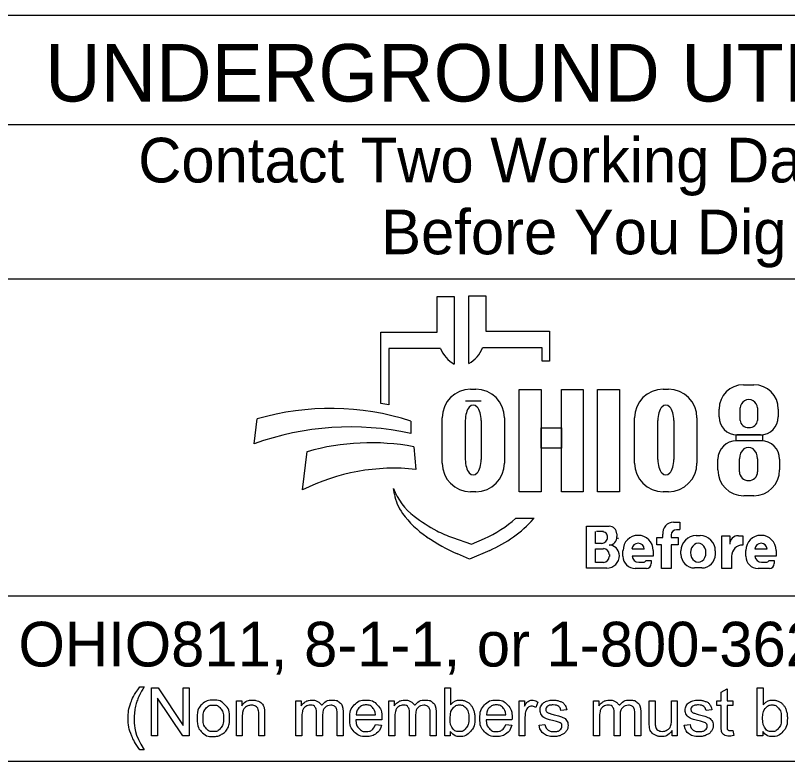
# Model space of a CAD drawing. Extents: x 0 to 170000, y 0 to 110000.
# Drawn here: x 11104 to 23197, y 15901 to 27588 of the extents above; entities that cross this region are included whole.
import ezdxf

# ---------------------------------------------------------------- set-up
doc = ezdxf.new("R2010")
doc.units = 0
doc.layers.add('SH_Data', color=7, linetype='Continuous')
doc.layers.add('SH_Text', color=7, linetype='Continuous')

msp = doc.modelspace()

# ---------------------------------------------------------------- linework, layer by layer
at = {"layer": 'SH_Data'}
for p, q in [((32179, 27588), (10929, 27588)), ((10929, 25880), (32179, 25880)), ((10929, 23463), (32179, 23463)), ((32179, 18490), (10929, 18490)), ((32179, 15901), (10929, 15901))]:
    msp.add_line(p, q, dxfattribs=at)
at = {"layer": 'SH_Text'}
for p, q in [((17709, 22628), (17709, 23186)), ((17709, 23186), (17977, 23186)), ((17977, 23186), (17977, 22125)), ((18205, 22137), (18205, 23197)), ((18205, 23197), (18474, 23197)), ((18474, 23197), (18474, 22640)), ((16829, 21509), (16829, 22628)), ((16829, 22628), (17709, 22628)), ((18474, 22640), (19470, 22640)), ((19470, 22640), (19470, 22171)), ((19353, 22383), (18422, 22383)), ((19353, 22171), (19353, 22383)), ((16955, 22371), (16955, 21487)), ((17761, 22371), (16955, 22371)), ((19470, 22171), (19353, 22171)), ((22507, 21802), (22670, 21802)), ((18234, 21732), (18316, 21732)), ((21249, 21732), (21332, 21732)), ((18400, 21547), (18151, 21547)), ((22125, 21299), (22125, 21421)), ((22456, 21242), (22456, 21439)), ((22727, 21439), (22727, 21242)), ((23052, 21421), (23052, 21299)), ((17786, 20575), (17786, 21285)), ((18764, 21285), (18764, 20575)), ((20802, 20575), (20802, 21285)), ((21779, 21285), (21779, 20575)), ((14842, 20877), (14889, 21268)), ((17296, 21235), (17296, 21041)), ((18151, 20632), (18151, 21243)), ((18400, 21243), (18400, 20632)), ((21166, 20632), (21166, 21243)), ((21415, 21243), (21415, 20632)), ((22396, 20928), (22783, 20928)), ((22772, 21019), (22405, 21019)), ((17345, 20832), (17376, 20478)), ((15601, 20155), (15675, 20755)), ((22107, 20468), (22107, 20638)), ((22444, 20438), (22444, 20643)), ((22728, 20643), (22728, 20438)), ((23072, 20638), (23072, 20468)), ((17040, 20090), (17025, 20180)), ((18316, 20127), (18234, 20127)), ((21332, 20127), (21249, 20127)), ((22667, 20063), (22511, 20063)), ((18941, 19711), (19228, 19711)), ((21411, 19649), (21508, 19649)), ((21508, 19649), (21508, 19535)), ((20048, 18932), (20048, 19586)), ((20048, 19586), (20404, 19586)), ((20188, 19318), (20188, 19503)), ((20314, 19503), (20207, 19503)), ((21508, 19532), (21457, 19532)), ((17949, 19409), (18246, 19306)), ((18246, 19306), (18451, 19395)), ((20522, 19467), (20522, 19427)), ((21148, 19293), (21148, 19408)), ((21148, 19408), (21244, 19408)), ((21244, 19408), (21244, 19460)), ((21375, 19450), (21375, 19408)), ((21375, 19408), (21483, 19408)), ((21483, 19408), (21483, 19293)), ((21767, 19440), (21827, 19440)), ((22168, 18926), (22168, 19439)), ((22168, 19439), (22291, 19439)), ((22291, 19439), (22291, 19305)), ((22427, 19439), (22496, 19439)), ((22496, 19439), (22496, 19291)), ((20285, 19318), (20188, 19318)), ((20188, 19021), (20188, 19235)), ((20188, 19235), (20315, 19235)), ((21222, 19293), (21148, 19293)), ((21222, 18926), (21222, 19293)), ((21483, 19293), (21375, 19293)), ((21375, 19293), (21375, 18926)), ((18216, 19071), (18029, 19153)), ((18532, 19209), (18216, 19071)), ((20406, 19145), (20406, 19113)), ((20563, 19130), (20563, 19129)), ((20620, 19116), (20620, 19208)), ((20953, 19228), (20761, 19228)), ((21093, 19119), (20761, 19119)), ((21093, 19208), (21093, 19119)), ((21528, 19147), (21528, 19201)), ((22066, 19201), (22066, 19147)), ((22321, 19117), (22321, 18926)), ((22545, 19116), (22545, 19208)), ((22878, 19228), (22685, 19228)), ((23018, 19119), (22686, 19119)), ((23018, 19208), (23018, 19119)), ((20314, 19021), (20188, 19021)), ((20866, 19023), (20936, 19023)), ((20979, 19051), (21063, 19051)), ((21063, 19051), (21063, 19002)), ((22790, 19023), (22861, 19023)), ((22904, 19051), (22988, 19051)), ((22988, 19051), (22988, 19002)), ((20366, 18932), (20048, 18932)), ((20987, 18926), (20810, 18926)), ((21375, 18926), (21222, 18926)), ((21853, 18934), (21742, 18934)), ((22321, 18926), (22168, 18926)), ((22912, 18926), (22735, 18926))]:
    msp.add_line(p, q, dxfattribs=at)
for points in [[(18996, 21727), (19336, 21727), (19336, 20127), (18996, 20127)], [(19657, 21727), (19996, 21727), (19996, 20127), (19657, 20127)], [(20223, 21727), (20567, 21727), (20567, 20127), (20223, 20127)], [(19336, 21128), (19657, 21128), (19657, 20808), (19336, 20808)], [(22394, 21019), (22803, 21019), (22803, 20927), (22394, 20927)]]:
    msp.add_lwpolyline(points, close=True, dxfattribs=at)
for points in [[(13052, 17070), (13118, 17070)], [(13235, 16306), (13235, 17057), (13337, 17057), (13732, 16467), (13732, 17057), (13827, 17057), (13827, 16306), (13725, 16306), (13330, 16896), (13330, 16306), (13235, 16306)], [(17913, 16306), (17828, 16306), (17828, 17057), (17920, 17057), (17920, 16789)], [(22808, 16306), (22723, 16306), (22723, 17057), (22815, 17057), (22815, 16789)], [(22157, 16466), (22157, 16779), (22089, 16779), (22089, 16850), (22157, 16850), (22157, 16985), (22250, 17040), (22250, 16850), (22342, 16850), (22342, 16779), (22250, 16779), (22250, 16460)], [(14565, 16306), (14565, 16850), (14648, 16850), (14648, 16773)], [(15497, 16306), (15497, 16850), (15580, 16850), (15580, 16774)], [(16954, 16306), (16954, 16850), (17037, 16850), (17037, 16774)], [(18993, 16306), (18993, 16850), (19076, 16850), (19076, 16768)], [(19288, 16833), (19256, 16748)], [(20159, 16306), (20159, 16850), (20242, 16850), (20242, 16774)], [(21031, 16513), (21031, 16850), (21123, 16850), (21123, 16549)], [(21379, 16559), (21379, 16850), (21471, 16850), (21471, 16306), (21389, 16306)], [(19738, 16710), (19648, 16698)], [(22011, 16710), (21921, 16698)], [(14657, 16603), (14657, 16306), (14565, 16306)], [(15007, 16641), (15007, 16306), (14915, 16306), (14915, 16637)], [(15589, 16588), (15589, 16306), (15497, 16306)], [(15913, 16622), (15913, 16306), (15821, 16306), (15821, 16660)], [(16235, 16680), (16235, 16306), (16143, 16306), (16143, 16649)], [(16440, 16630), (16744, 16630)], [(17046, 16588), (17046, 16306), (16954, 16306)], [(17370, 16622), (17370, 16306), (17278, 16306), (17278, 16660)], [(17692, 16680), (17692, 16306), (17600, 16306), (17600, 16649)], [(18480, 16630), (18784, 16630)], [(19085, 16591), (19085, 16306), (18993, 16306)], [(20251, 16588), (20251, 16306), (20159, 16306)], [(20575, 16622), (20575, 16306), (20483, 16306), (20483, 16660)], [(20897, 16680), (20897, 16306), (20805, 16306), (20805, 16649)], [(16841, 16555), (16435, 16555)], [(16743, 16482), (16839, 16470)], [(18881, 16555), (18475, 16555)], [(18783, 16482), (18878, 16470)], [(19306, 16469), (19397, 16483)], [(21579, 16469), (21670, 16483)], [(17913, 16374), (17913, 16306)], [(21389, 16306), (21389, 16387)], [(22342, 16388), (22355, 16307)], [(22808, 16374), (22808, 16306)], [(13118, 16085), (13052, 16085)]]:
    msp.add_lwpolyline(points, dxfattribs=at)
for centre, radius, start, end in [((17965, 22566), 492, 299.2531, 338.0704), ((18218, 22555), 492, 201.9296, 240.7469), ((22507, 21421), 382, 90, 180), ((22670, 21421), 382, 0, 90), ((18234, 21285), 447, 90, 180), ((18316, 21285), 447, 0, 90), ((21249, 21285), 447, 90, 180), ((21332, 21285), 447, 0, 90), ((16040, 17337), 4095, 72.1402, 106.3144), ((16188, 17464), 4095, 79.2074, 81.0007), ((22405, 21299), 280, 180, 270), ((22772, 21299), 280, 270, 0), ((16355, 16682), 4460, 77.8238, 109.8274), ((22396, 20638), 289, 90, 180), ((22783, 20638), 289, 0, 90), ((16674, 17233), 3661, 79.44, 105.8467), ((18234, 20575), 447, 180, 270), ((18316, 20575), 447, 270, 0), ((21249, 20575), 447, 180, 270), ((21332, 20575), 447, 270, 0), ((17035, 17317), 3179, 83.8248, 116.8021), ((22511, 20468), 405, 180, 270), ((22667, 20468), 405, 270, 0), ((17961, 20540), 1004, 201.0457, 232.5314), ((17746, 20211), 717, 189.6817, 216.0884), ((18415, 20698), 1544, 216.0884, 235.7167), ((18924, 21796), 2586, 232.5314, 241.794), ((17734, 21048), 1801, 293.4582, 312.0712), ((17734, 21048), 2005, 293.4582, 317.8286), ((21411, 19482), 168, 90, 187.5187), ((18498, 21002), 1685, 241.794, 250.9821), ((20294, 19418), 84.4, 357.8325, 90), ((20404, 19467), 119, 0, 90), ((21457, 19450), 82.4, 90, 180), ((19247, 21919), 3022, 235.7167, 246.2325), ((20285, 19412), 93.6, 270, 2.0582), ((20402, 19413), 122, 270, 6.6529), ((20455, 19406), 87.6, 347.4023, 0), ((20857, 19208), 236, 0, 180), ((21767, 19201), 239, 90, 180), ((21827, 19201), 239, 0, 90), ((22425, 19305), 134, 89.2449, 180), ((22781, 19208), 236, 0, 180), ((20315, 19145), 90.6, 0, 90), ((20402, 19131), 160, 4.0748, 90), ((20857, 19223), 96.4, 2.9632, 177.0368), ((22495, 19117), 175, 89.6033, 180), ((22782, 19223), 96.4, 2.9632, 177.0368), ((20314, 19113), 91.9, 270, 0), ((20366, 19129), 197, 270, 0), ((20398, 19130), 165, 0, 11.7502), ((20810, 19116), 190, 180, 270), ((20866, 19128), 105, 184.827, 270), ((21742, 19147), 214, 180, 270), ((21853, 19147), 214, 270, 0), ((22735, 19116), 190, 180, 270), ((22790, 19128), 105, 184.827, 270), ((20936, 19070), 46.9, 270, 335.9979), ((20987, 19002), 76.1, 270, 0), ((22861, 19070), 46.9, 270, 335.9979), ((22912, 19002), 76.1, 270, 0)]:
    msp.add_arc(centre, radius, start, end, dxfattribs=at)
for centre, major_axis, ratio, start_param, end_param in [((22591, 21439), (135, 0), 0.969373, 0, 3.141593), ((18275, 21243), (0, 242), 0.514403, 4.712389, 7.853982), ((21291, 21243), (0, 242), 0.514403, 4.712389, 7.853982), ((22591, 21242), (135, 0), 0.818453, 3.141593, 6.283185), ((22586, 20643), (0, 179), 0.794529, 4.712389, 7.853982), ((18275, 20632), (0, 242), 0.514403, 1.570796, 4.712389), ((21291, 20632), (0, 242), 0.514403, 1.570796, 4.712389), ((22586, 20438), (142, 0), 0.959837, 3.141593, 6.283185), ((21799, 19174), (0, 145), 0.832186, 4.712389, 7.853982), ((21799, 19174), (0, 151), 0.797287, 1.570796, 4.712389)]:
    msp.add_ellipse(centre, major_axis=major_axis, ratio=ratio, start_param=start_param, end_param=end_param, dxfattribs=at)
for points in [[(13052, 16085), (12975, 16182), (12923, 16311), (12870, 16440), (12870, 16578), (12870, 16700), (12909, 16812), (12955, 16941), (13052, 17070)], [(13118, 17070), (13056, 16963), (13036, 16918), (13005, 16847), (12987, 16770), (12965, 16674), (12965, 16578), (12965, 16331), (13118, 16085)], [(13948, 16578), (13948, 16729), (14032, 16802), (14102, 16862), (14203, 16862), (14315, 16862), (14386, 16789), (14457, 16716), (14457, 16586), (14457, 16481), (14426, 16421), (14394, 16361), (14334, 16328), (14274, 16294), (14203, 16294), (14089, 16294), (14018, 16367), (13948, 16441), (13948, 16578)], [(14648, 16773), (14708, 16862), (14821, 16862), (14870, 16862), (14912, 16845), (14953, 16827), (14973, 16798), (14994, 16770), (15002, 16730), (15007, 16705), (15007, 16641)], [(15580, 16774), (15605, 16814), (15648, 16838), (15690, 16862), (15745, 16862), (15805, 16862), (15844, 16837), (15883, 16812), (15898, 16767), (15963, 16862), (16067, 16862), (16148, 16862), (16191, 16818), (16235, 16773), (16235, 16680)], [(16839, 16470), (16816, 16386), (16755, 16340), (16694, 16294), (16599, 16294), (16480, 16294), (16410, 16368), (16340, 16441), (16340, 16574), (16340, 16711), (16411, 16787), (16482, 16862), (16594, 16862), (16703, 16862), (16772, 16788), (16842, 16714), (16842, 16579), (16842, 16571), (16841, 16555)], [(17037, 16774), (17062, 16814), (17105, 16838), (17147, 16862), (17202, 16862), (17262, 16862), (17301, 16837), (17339, 16812), (17355, 16767), (17420, 16862), (17524, 16862), (17605, 16862), (17648, 16818), (17692, 16773), (17692, 16680)], [(17920, 16789), (17978, 16862), (18069, 16862), (18119, 16862), (18164, 16842), (18208, 16822), (18237, 16785), (18266, 16749), (18283, 16697), (18299, 16645), (18299, 16587), (18299, 16447), (18230, 16371), (18161, 16294), (18064, 16294), (17968, 16294), (17913, 16374)], [(18878, 16470), (18856, 16386), (18795, 16340), (18734, 16294), (18639, 16294), (18520, 16294), (18450, 16368), (18380, 16441), (18380, 16574), (18380, 16711), (18451, 16787), (18522, 16862), (18634, 16862), (18743, 16862), (18812, 16788), (18882, 16714), (18882, 16579), (18882, 16571), (18881, 16555)], [(19076, 16768), (19108, 16826), (19135, 16844), (19162, 16862), (19194, 16862), (19240, 16862), (19288, 16833)], [(19397, 16483), (19405, 16428), (19440, 16399), (19475, 16370), (19538, 16370), (19602, 16370), (19633, 16396), (19664, 16422), (19664, 16456), (19664, 16488), (19637, 16506), (19617, 16518), (19542, 16537), (19441, 16563), (19401, 16581), (19362, 16600), (19342, 16633), (19322, 16666), (19322, 16706), (19322, 16742), (19338, 16773), (19355, 16804), (19384, 16825), (19405, 16840), (19442, 16851), (19480, 16862), (19522, 16862), (19586, 16862), (19635, 16844), (19683, 16826), (19706, 16794), (19729, 16762), (19738, 16710)], [(20242, 16774), (20267, 16814), (20310, 16838), (20352, 16862), (20407, 16862), (20467, 16862), (20506, 16837), (20544, 16812), (20560, 16767), (20625, 16862), (20729, 16862), (20810, 16862), (20853, 16818), (20897, 16773), (20897, 16680)], [(21670, 16483), (21678, 16428), (21713, 16399), (21748, 16370), (21811, 16370), (21875, 16370), (21906, 16396), (21937, 16422), (21937, 16456), (21937, 16488), (21909, 16506), (21890, 16518), (21815, 16537), (21713, 16563), (21674, 16581), (21635, 16600), (21615, 16633), (21594, 16666), (21594, 16706), (21594, 16742), (21611, 16773), (21628, 16804), (21656, 16825), (21678, 16840), (21715, 16851), (21752, 16862), (21795, 16862), (21859, 16862), (21908, 16844), (21956, 16826), (21979, 16794), (22002, 16762), (22011, 16710)], [(22815, 16789), (22873, 16862), (22964, 16862), (23014, 16862), (23059, 16842), (23104, 16822), (23133, 16785), (23162, 16749), (23178, 16697), (23194, 16645), (23194, 16587), (23194, 16447), (23125, 16371), (23056, 16294), (22959, 16294), (22863, 16294), (22808, 16374)], [(14043, 16578), (14043, 16474), (14088, 16422), (14134, 16370), (14203, 16370), (14271, 16370), (14317, 16422), (14362, 16474), (14362, 16581), (14362, 16682), (14316, 16734), (14271, 16786), (14203, 16786), (14134, 16786), (14088, 16735), (14043, 16683), (14043, 16578)], [(14915, 16637), (14915, 16693), (14904, 16721), (14893, 16749), (14866, 16766), (14839, 16782), (14802, 16782), (14743, 16782), (14700, 16745), (14657, 16708), (14657, 16603)], [(15821, 16660), (15821, 16721), (15798, 16752), (15776, 16782), (15724, 16782), (15685, 16782), (15652, 16762), (15619, 16741), (15604, 16702), (15589, 16663), (15589, 16588)], [(16143, 16649), (16143, 16704), (16134, 16728), (16125, 16753), (16101, 16768), (16078, 16782), (16046, 16782), (15989, 16782), (15951, 16744), (15913, 16706), (15913, 16622)], [(16744, 16630), (16738, 16699), (16709, 16733), (16665, 16787), (16595, 16787), (16532, 16787), (16488, 16744), (16445, 16702), (16440, 16630)], [(17278, 16660), (17278, 16721), (17255, 16752), (17232, 16782), (17181, 16782), (17142, 16782), (17109, 16762), (17076, 16741), (17061, 16702), (17046, 16663), (17046, 16588)], [(17600, 16649), (17600, 16704), (17591, 16728), (17582, 16753), (17558, 16768), (17535, 16782), (17503, 16782), (17445, 16782), (17408, 16744), (17370, 16706), (17370, 16622)], [(17912, 16582), (17912, 16485), (17938, 16441), (17982, 16370), (18056, 16370), (18116, 16370), (18160, 16422), (18204, 16475), (18204, 16579), (18204, 16685), (18162, 16736), (18120, 16787), (18060, 16787), (18000, 16787), (17956, 16734), (17912, 16682), (17912, 16582)], [(18784, 16630), (18778, 16699), (18749, 16733), (18705, 16787), (18635, 16787), (18572, 16787), (18528, 16744), (18485, 16702), (18480, 16630)], [(19256, 16748), (19222, 16767), (19189, 16767), (19159, 16767), (19135, 16749), (19111, 16731), (19101, 16699), (19085, 16650), (19085, 16591)], [(19648, 16698), (19642, 16740), (19612, 16763), (19583, 16787), (19529, 16787), (19465, 16787), (19438, 16766), (19411, 16745), (19411, 16717), (19411, 16699), (19422, 16684), (19433, 16669), (19458, 16660), (19471, 16655), (19539, 16636), (19637, 16610), (19676, 16593), (19715, 16577), (19737, 16545), (19759, 16513), (19759, 16466), (19759, 16420), (19732, 16379), (19705, 16339), (19654, 16317), (19603, 16294), (19539, 16294), (19433, 16294), (19377, 16338), (19322, 16382), (19306, 16469)], [(20483, 16660), (20483, 16721), (20460, 16752), (20437, 16782), (20386, 16782), (20347, 16782), (20314, 16762), (20281, 16741), (20266, 16702), (20251, 16663), (20251, 16588)], [(20805, 16649), (20805, 16704), (20796, 16728), (20787, 16753), (20763, 16768), (20740, 16782), (20708, 16782), (20650, 16782), (20613, 16744), (20575, 16706), (20575, 16622)], [(21921, 16698), (21914, 16740), (21885, 16763), (21855, 16787), (21802, 16787), (21738, 16787), (21711, 16766), (21684, 16745), (21684, 16717), (21684, 16699), (21695, 16684), (21706, 16669), (21730, 16660), (21744, 16655), (21812, 16636), (21910, 16610), (21949, 16593), (21987, 16577), (22010, 16545), (22032, 16513), (22032, 16466), (22032, 16420), (22005, 16379), (21978, 16339), (21927, 16317), (21876, 16294), (21812, 16294), (21706, 16294), (21650, 16338), (21594, 16382), (21579, 16469)], [(22807, 16582), (22807, 16485), (22834, 16441), (22877, 16370), (22951, 16370), (23011, 16370), (23055, 16422), (23099, 16475), (23099, 16579), (23099, 16685), (23057, 16736), (23015, 16787), (22955, 16787), (22895, 16787), (22851, 16734), (22807, 16682), (22807, 16582)], [(16435, 16555), (16440, 16465), (16486, 16417), (16532, 16370), (16600, 16370), (16651, 16370), (16686, 16397), (16722, 16423), (16743, 16482)], [(18475, 16555), (18480, 16465), (18526, 16417), (18572, 16370), (18640, 16370), (18690, 16370), (18726, 16397), (18762, 16423), (18783, 16482)], [(21389, 16387), (21326, 16294), (21217, 16294), (21168, 16294), (21127, 16313), (21085, 16331), (21065, 16359), (21045, 16387), (21036, 16427), (21031, 16455), (21031, 16513)], [(21123, 16549), (21123, 16477), (21129, 16452), (21137, 16415), (21165, 16395), (21194, 16374), (21235, 16374), (21276, 16374), (21313, 16395), (21349, 16416), (21364, 16453), (21379, 16490), (21379, 16559)], [(22355, 16307), (22316, 16299), (22285, 16299), (22235, 16299), (22208, 16315), (22180, 16331), (22169, 16357), (22157, 16382), (22157, 16466)], [(22250, 16460), (22250, 16421), (22254, 16409), (22259, 16398), (22270, 16391), (22281, 16385), (22302, 16385), (22317, 16385), (22342, 16388)]]:
    msp.add_open_spline(points, degree=3, dxfattribs=at)

# ---------------------------------------------------------------- texts
for s, height, p in [('UNDERGROUND UTILITIES', 900, (11569, 26240)), ('Contact Two Working Days', 700, (13027, 24972)), ('Before You Dig', 700, (16833, 23847)), ('OHIO811, 8-1-1, or 1-800-362-2764', 700, (11151, 17390))]:
    msp.add_text(s, height=height, dxfattribs=at).set_placement(p)

doc.saveas('drawing.dxf')
